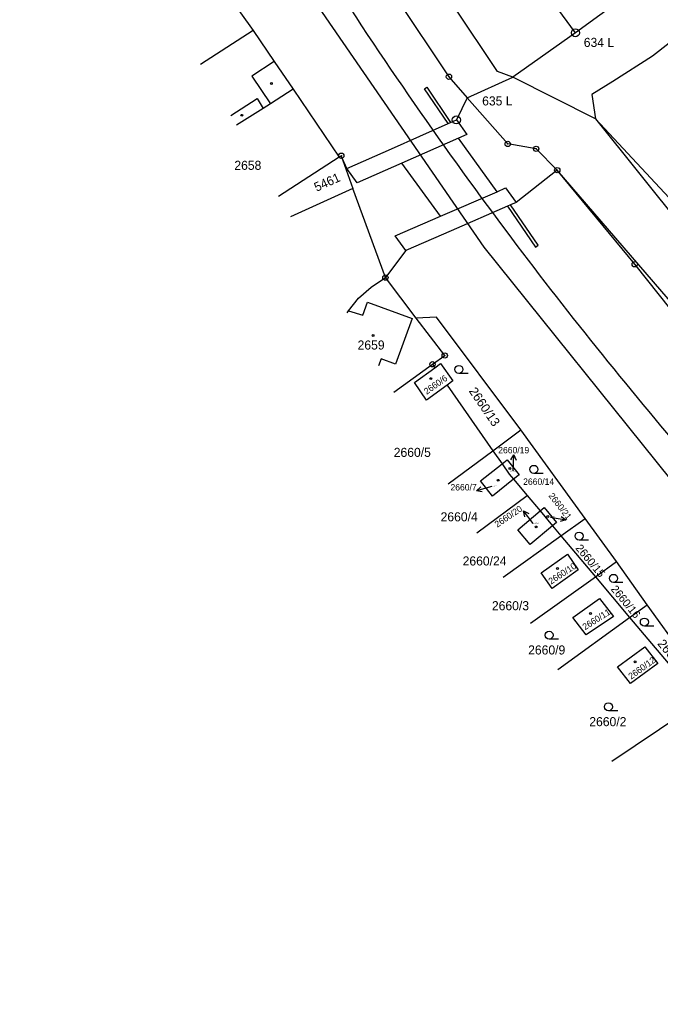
# Model space of a CAD drawing. Extents: x -825057 to -819383, y -1071633 to -1067888.
# Drawn here: x -820648.4 to -820528.4, y -1071451.9 to -1071267 of the extents above; entities that cross this region are included whole.
import ezdxf

# ---------------------------------------------------------------- set-up
doc = ezdxf.new("R2010")
doc.units = 0
for name, color, linetype in [('Vrstva 1', 7, 'Continuous'), ('Vrstva 10', 7, 'Continuous'), ('Vrstva 16', 7, 'Continuous'), ('Vrstva 17', 7, 'Continuous'), ('Vrstva 18', 7, 'Continuous'), ('Vrstva 19', 7, 'Continuous'), ('Vrstva 24', 7, 'Continuous'), ('Vrstva 25', 7, 'Continuous'), ('Vrstva 4', 7, 'Continuous')]:
    doc.layers.add(name, color=color, linetype=linetype)

msp = doc.modelspace()

# ---------------------------------------------------------------- linework, layer by layer
at = {"layer": 'Vrstva 1'}
for p, q in [((-820613.1, -1071210.27), (-820567.96, -1071277.63)), ((-820612.18, -1071258.39), (-820604.65, -1071268.97)), ((-820534.83, -1071262.53), (-820544.28, -1071269.4)), ((-820558.89, -1071276.65), (-820567.06, -1071264.43)), ((-820604.65, -1071268.97), (-820614.48, -1071275.35)), ((-820604.65, -1071268.97), (-820600.69, -1071274.81)), ((-820522.97, -1071268.41), (-820529.82, -1071273.81)), ((-820544.28, -1071269.4), (-820555.99, -1071277.72)), ((-820529.82, -1071273.81), (-820537.27, -1071278.55)), ((-820600.69, -1071274.81), (-820597.17, -1071279.98)), ((-820555.99, -1071277.72), (-820558.89, -1071276.65)), ((-820567.96, -1071277.63), (-820564.58, -1071281.57)), ((-820564.58, -1071281.57), (-820555.99, -1071277.72)), ((-820540.54, -1071285.54), (-820555.99, -1071277.72)), ((-820597.17, -1071279.98), (-820601.4, -1071282.71)), ((-820597.17, -1071279.98), (-820588.5, -1071292.71)), ((-820537.27, -1071278.55), (-820541.2, -1071280.96)), ((-820556.95, -1071290.24), (-820564.58, -1071281.57)), ((-820541.2, -1071280.96), (-820540.54, -1071285.54)), ((-820602.74, -1071283.57), (-820607.78, -1071286.72)), ((-820601.4, -1071282.71), (-820602.74, -1071283.57)), ((-820540.54, -1071285.54), (-820522.19, -1071305.22)), ((-820551.62, -1071291.15), (-820556.95, -1071290.24)), ((-820547.67, -1071295.15), (-820551.62, -1071291.15)), ((-820588.5, -1071292.71), (-820599.87, -1071300.11)), ((-820588.5, -1071292.71), (-820588.13, -1071292.45)), ((-820588.13, -1071292.45), (-820585.94, -1071298.56)), ((-820533.17, -1071312.78), (-820547.67, -1071295.15)), ((-820585.94, -1071298.56), (-820597.63, -1071303.91)), ((-820579.87, -1071315.28), (-820585.94, -1071298.56)), ((-820483.1, -1071375.86), (-820533.17, -1071312.78)), ((-820582.56, -1071317.06), (-820579.87, -1071315.28)), ((-820574.1, -1071322.9), (-820579.87, -1071315.28)), ((-820584.9, -1071319.14), (-820582.56, -1071317.06)), ((-820586.78, -1071321.49), (-820584.9, -1071319.14)), ((-820587.02, -1071321.89), (-820586.78, -1071321.49)), ((-820570.3, -1071322.7), (-820574.1, -1071322.9)), ((-820554.5, -1071343.84), (-820570.3, -1071322.7)), ((-820568.75, -1071329.89), (-820574.1, -1071322.9)), ((-820571.04, -1071331.54), (-820568.75, -1071329.89)), ((-820578.26, -1071336.74), (-820571.04, -1071331.54)), ((-820571.04, -1071331.54), (-820570.59, -1071332.17)), ((-820570.59, -1071332.17), (-820569.54, -1071331.41)), ((-820569.54, -1071331.41), (-820567.24, -1071334.63)), ((-820574.43, -1071334.97), (-820570.59, -1071332.17)), ((-820572.14, -1071338.27), (-820574.43, -1071334.97)), ((-820568.32, -1071335.44), (-820572.14, -1071338.27)), ((-820567.24, -1071334.63), (-820568.32, -1071335.44)), ((-820568.32, -1071335.44), (-820559.74, -1071347.73)), ((-820559.74, -1071347.73), (-820554.5, -1071343.84)), ((-820542.47, -1071360.42), (-820554.5, -1071343.84)), ((-820568.11, -1071353.95), (-820559.74, -1071347.73)), ((-820559.74, -1071347.73), (-820558.02, -1071350.19)), ((-820562.06, -1071353.35), (-820558.02, -1071350.19)), ((-820558.02, -1071350.19), (-820557.03, -1071349.41)), ((-820558.02, -1071350.19), (-820556.66, -1071352.14)), ((-820557.03, -1071349.41), (-820554.83, -1071352.23)), ((-820556.66, -1071352.14), (-820555.87, -1071353.08)), ((-820554.83, -1071352.23), (-820555.87, -1071353.08)), ((-820559.79, -1071356.27), (-820562.06, -1071353.35)), ((-820555.87, -1071353.08), (-820559.79, -1071356.27)), ((-820555.87, -1071353.08), (-820553.32, -1071356.12)), ((-820562.71, -1071363.09), (-820553.32, -1071356.12)), ((-820553.32, -1071356.12), (-820550.89, -1071359.01)), ((-820555.08, -1071362.55), (-820550.89, -1071359.01)), ((-820550.89, -1071359.01), (-820550.13, -1071358.37)), ((-820550.89, -1071359.01), (-820548.54, -1071361.81)), ((-820550.13, -1071358.37), (-820547.79, -1071361.2)), ((-820547.79, -1071361.2), (-820548.54, -1071361.81)), ((-820546.99, -1071363.66), (-820542.47, -1071360.42)), ((-820536.6, -1071368.5), (-820542.47, -1071360.42)), ((-820552.75, -1071365.3), (-820555.08, -1071362.55)), ((-820548.54, -1071361.81), (-820552.75, -1071365.3)), ((-820548.54, -1071361.81), (-820546.99, -1071363.66)), ((-820557.81, -1071371.4), (-820546.99, -1071363.66)), ((-820546.99, -1071363.66), (-820540.54, -1071371.34)), ((-820550.69, -1071370.64), (-820545.77, -1071367.15)), ((-820545.77, -1071367.15), (-820543.74, -1071370.03)), ((-820540.54, -1071371.34), (-820536.6, -1071368.5)), ((-820530.86, -1071376.6), (-820536.6, -1071368.5)), ((-820548.64, -1071373.54), (-820550.69, -1071370.64)), ((-820543.74, -1071370.03), (-820548.64, -1071373.54)), ((-820552.68, -1071380.08), (-820540.54, -1071371.34)), ((-820540.54, -1071371.34), (-820534.12, -1071378.97)), ((-820544.75, -1071379.02), (-820539.74, -1071375.45)), ((-820539.74, -1071375.45), (-820537.14, -1071378.82)), ((-820534.12, -1071378.97), (-820530.86, -1071376.6)), ((-820518.8, -1071393.3), (-820530.86, -1071376.6)), ((-820547.57, -1071388.74), (-820534.12, -1071378.97)), ((-820542.28, -1071382.23), (-820544.75, -1071379.02)), ((-820537.14, -1071378.82), (-820542.28, -1071382.23)), ((-820534.12, -1071378.97), (-820522.21, -1071393.16)), ((-820536.4, -1071388.26), (-820531.29, -1071384.48)), ((-820531.29, -1071384.48), (-820528.82, -1071387.59)), ((-820528.82, -1071387.59), (-820533.93, -1071391.38)), ((-820533.93, -1071391.38), (-820536.4, -1071388.26)), ((-820537.43, -1071405.94), (-820520.45, -1071394.42))]:
    msp.add_line(p, q, dxfattribs=at)
at = {"layer": 'Vrstva 10'}
for p, q in [((-820561.35, -1071309.57), (-820596.75, -1071258.19)), ((-820526.35, -1071353.17), (-820561.35, -1071309.57))]:
    msp.add_line(p, q, dxfattribs=at)
msp.add_spline([(-820648.37, -1071145.75), (-820635.21, -1071175.92), (-820619.77, -1071208), (-820606.88, -1071231.72), (-820592.84, -1071254.92), (-820557.31, -1071306.48), (-820522.72, -1071349.67), (-820487.72, -1071388.36), (-820440.04, -1071434.15), (-820382.01, -1071481.32), (-820258.78, -1071573.12)], degree=3, dxfattribs=at)
at = {"layer": 'Vrstva 16'}
for p, q in [((-820555.95, -1071351.47), (-820555.79, -1071348.474)), ((-820559.91, -1071354.46), (-820562.808, -1071355.235)), ((-820552.16, -1071361.39), (-820553.974, -1071359.001)), ((-820548.97, -1071360.21), (-820546.067, -1071360.672))]:
    msp.add_line(p, q, dxfattribs=at)
for points in [[(-820556.342, -1071349.446), (-820555.79, -1071348.474), (-820555.344, -1071349.5)], [(-820561.713, -1071355.46), (-820562.808, -1071355.235), (-820561.971, -1071354.494)], [(-820553.768, -1071360.1), (-820553.974, -1071359.001), (-820552.971, -1071359.495)], [(-820546.957, -1071360.034), (-820546.067, -1071360.672), (-820547.111, -1071361.002)]]:
    msp.add_lwpolyline(points, dxfattribs=at)
at = {"layer": 'Vrstva 24'}
for centre, radius in [((-820544.28, -1071269.4), 0.75), ((-820544.28, -1071269.4), 0.0327), ((-820567.96, -1071277.63), 0.5), ((-820567.96, -1071277.63), 0.0327), ((-820566.58, -1071285.74), 0.75), ((-820566.58, -1071285.74), 0.0327), ((-820556.95, -1071290.24), 0.5), ((-820556.95, -1071290.24), 0.0327), ((-820551.62, -1071291.15), 0.5), ((-820551.62, -1071291.15), 0.0327), ((-820588.13, -1071292.45), 0.5), ((-820588.13, -1071292.45), 0.0327), ((-820547.67, -1071295.15), 0.5), ((-820547.67, -1071295.15), 0.0327), ((-820533.17, -1071312.78), 0.5), ((-820533.17, -1071312.78), 0.0327), ((-820579.87, -1071315.28), 0.5), ((-820579.87, -1071315.28), 0.0327), ((-820568.75, -1071329.89), 0.5), ((-820568.75, -1071329.89), 0.0327), ((-820571.04, -1071331.54), 0.5), ((-820571.04, -1071331.54), 0.0327)]:
    msp.add_circle(centre, radius, dxfattribs=at)
at = {"layer": 'Vrstva 25'}
for p, q in [((-820564.36, -1071333.24), (-820566.11, -1071333.24)), ((-820550.31, -1071351.97), (-820552.06, -1071351.97)), ((-820541.83, -1071364.48), (-820543.58, -1071364.48)), ((-820535.38, -1071372.4), (-820537.13, -1071372.4)), ((-820529.61, -1071380.6), (-820531.36, -1071380.6)), ((-820547.44, -1071383.05), (-820549.19, -1071383.05)), ((-820536.33, -1071396.48), (-820538.08, -1071396.48))]:
    msp.add_line(p, q, dxfattribs=at)
for centre, radius in [((-820601.23, -1071278.91), 0.175), ((-820606.75, -1071284.87), 0.175), ((-820582.19, -1071326.15), 0.175), ((-820566.11, -1071332.49), 0.75), ((-820571.36, -1071334.22), 0.175), ((-820552.06, -1071351.22), 0.75), ((-820556.53, -1071351.07), 0.175), ((-820558.76, -1071353.27), 0.175), ((-820549.45, -1071360.07), 0.175), ((-820551.65, -1071362.02), 0.175), ((-820543.58, -1071363.73), 0.75), ((-820547.62, -1071369.82), 0.175), ((-820537.13, -1071371.65), 0.75), ((-820541.44, -1071378.24), 0.175), ((-820531.36, -1071379.85), 0.75), ((-820549.19, -1071382.3), 0.75), ((-820533.1, -1071387.3), 0.175), ((-820538.08, -1071395.73), 0.75)]:
    msp.add_circle(centre, radius, dxfattribs=at)
at = {"layer": 'Vrstva 4'}
for p, q in [((-820544.28, -1071269.4), (-820550.56, -1071260.76)), ((-820600.69, -1071274.81), (-820604.89, -1071277.55)), ((-820604.89, -1071277.55), (-820601.4, -1071282.71)), ((-820572.54, -1071279.89), (-820572.13, -1071279.61)), ((-820568.13, -1071286.43), (-820572.54, -1071279.89)), ((-820572.13, -1071279.61), (-820567.68, -1071286.23)), ((-820608.85, -1071284.9), (-820603.91, -1071281.72)), ((-820603.91, -1071281.72), (-820602.74, -1071283.57)), ((-820564.58, -1071281.57), (-820566.58, -1071285.74)), ((-820567.68, -1071286.23), (-820566.58, -1071285.74)), ((-820566.58, -1071285.74), (-820564.61, -1071288.46)), ((-820540.54, -1071285.54), (-820479.66, -1071361.53)), ((-820578.74, -1071291.13), (-820568.13, -1071286.43)), ((-820568.13, -1071286.43), (-820567.68, -1071286.23)), ((-820566.17, -1071289.15), (-820576.77, -1071293.84)), ((-820564.61, -1071288.46), (-820566.17, -1071289.15)), ((-820558.94, -1071299.19), (-820566.17, -1071289.15)), ((-820587.08, -1071294.82), (-820578.74, -1071291.13)), ((-820587.08, -1071294.82), (-820588.13, -1071292.45)), ((-820585.13, -1071297.55), (-820587.08, -1071294.82)), ((-820576.77, -1071293.84), (-820585.13, -1071297.55)), ((-820569.54, -1071303.79), (-820576.77, -1071293.84)), ((-820547.67, -1071295.15), (-820555.37, -1071301.21)), ((-820486.8, -1071365.91), (-820547.67, -1071295.15)), ((-820558.94, -1071299.19), (-820557.34, -1071298.49)), ((-820557.34, -1071298.49), (-820555.37, -1071301.21)), ((-820569.54, -1071303.79), (-820558.94, -1071299.19)), ((-820556.98, -1071301.91), (-820567.57, -1071306.5)), ((-820556.42, -1071301.67), (-820556.98, -1071301.91)), ((-820556.98, -1071301.91), (-820551.77, -1071309.57)), ((-820555.37, -1071301.21), (-820556.42, -1071301.67)), ((-820551.27, -1071309.23), (-820556.42, -1071301.67)), ((-820578.01, -1071307.47), (-820569.54, -1071303.79)), ((-820576.06, -1071310.19), (-820578.01, -1071307.47)), ((-820567.57, -1071306.5), (-820576.06, -1071310.19)), ((-820551.77, -1071309.57), (-820551.27, -1071309.23)), ((-820576.06, -1071310.19), (-820579.87, -1071315.28)), ((-820584.11, -1071322.31), (-820583.2, -1071319.9)), ((-820583.2, -1071319.9), (-820574.86, -1071322.92)), ((-820586.78, -1071321.49), (-820584.11, -1071322.31)), ((-820574.86, -1071322.92), (-820577.97, -1071331.52)), ((-820580.66, -1071330.52), (-820581.15, -1071331.84)), ((-820577.97, -1071331.52), (-820580.66, -1071330.52))]:
    msp.add_line(p, q, dxfattribs=at)

# ---------------------------------------------------------------- texts
at = {"layer": 'Vrstva 16'}
for s, p in [('2660/19', (-820558.73, -1071348.22)), ('2660/7', (-820567.68, -1071355.18))]:
    msp.add_text(s, height=1.2, dxfattribs=at).set_placement(p)
for s, rotation, p in [('2660/21', 307.8, (-820549.38, -1071356.19)), ('2660/20', 34.2, (-820558.9, -1071362.17))]:
    msp.add_text(s, height=1.2, rotation=rotation, dxfattribs=at).set_placement(p)
at = {"layer": 'Vrstva 17'}
for s, p in [('634 L', (-820542.706, -1071272.05)), ('635 L', (-820561.746, -1071283.02))]:
    msp.add_text(s, height=1.7, dxfattribs=at).set_placement(p)
at = {"layer": 'Vrstva 18'}
for s, height, p in [('2658', 1.7, (-820608.166, -1071295.09)), ('2660/5', 1.7, (-820578.307, -1071348.89)), ('2660/14', 1.2, (-820554.06, -1071354.13)), ('2660/4', 1.7, (-820569.526, -1071360.97)), ('2660/24', 1.7, (-820565.399, -1071369.24)), ('2660/3', 1.7, (-820559.912, -1071377.63)), ('2660/9', 1.7, (-820553.126, -1071385.92)), ('2660/2', 1.7, (-820541.671, -1071399.36))]:
    msp.add_text(s, height=height, dxfattribs=at).set_placement(p)
for s, height, rotation, p in [('5461', 1.7, 24.3, (-820592.753, -1071299.22)), ('2660/13', 1.7, 304.2, (-820564.307, -1071336.556)), ('2660/15', 1.5, 309.6, (-820544.345, -1071366.036)), ('2660/16', 1.5, 309.6, (-820537.736, -1071373.719)), ('2660/17', 1.7, 309.6, (-820529.005, -1071383.944))]:
    msp.add_text(s, height=height, rotation=rotation, dxfattribs=at).set_placement(p)
at = {"layer": 'Vrstva 19'}
for s, height, p in [('2659', 1.7, (-820585.078, -1071328.77)), ('2660/19', 0.2, (-820556.47, -1071351.63)), ('2660/7', 0.2, (-820559.91, -1071354.46)), ('2660/20', 0.2, (-820552.16, -1071361.39)), ('2660/21', 0.2, (-820548.97, -1071360.21))]:
    msp.add_text(s, height=height, dxfattribs=at).set_placement(p)
for s, rotation, p in [('2660/6', 35.1, (-820572.13, -1071337.26)), ('2660/10', 33.3, (-820548.82, -1071372.83)), ('2660/11', 32.4, (-820542.47, -1071381.39)), ('2660/12', 36, (-820533.82, -1071390.65))]:
    msp.add_text(s, height=1.2, rotation=rotation, dxfattribs=at).set_placement(p)

doc.saveas('drawing.dxf')
